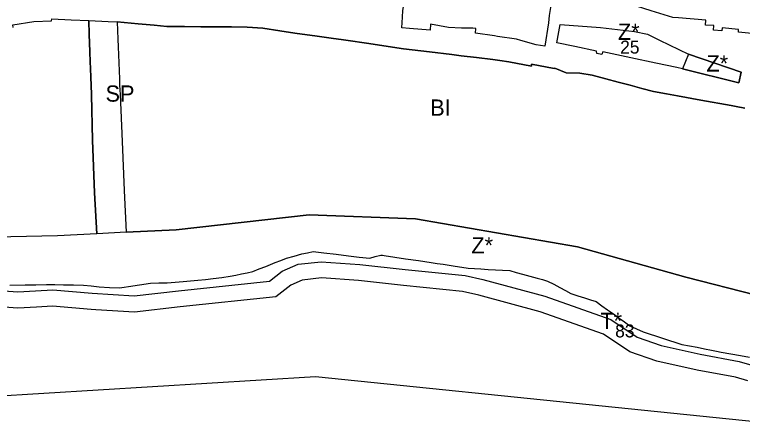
# Model space of a CAD drawing. Extents: x -521621 to -516769, y -1190068 to -1185078.
# Drawn here: x -519976.5 to -519527.8, y -1187499.7 to -1187252.5 of the extents above; entities that cross this region are included whole.
import ezdxf

# ---------------------------------------------------------------- set-up
doc = ezdxf.new("R2010")
doc.units = 0
for name, color, linetype in [('bydleni_s', 7, 'Continuous'), ('fpl_id', 7, 'Continuous'), ('s_zelen_n', 7, 'Continuous'), ('s_zelen_s', 7, 'Continuous'), ('sm_vyuziti_s', 7, 'Continuous'), ('v_infrastr_n', 7, 'Continuous'), ('v_infrastr_s', 7, 'Continuous')]:
    doc.layers.add(name, color=color, linetype=linetype)

msp = doc.modelspace()

# ---------------------------------------------------------------- linework, layer by layer
at = {"layer": 'bydleni_s'}
for p, q in [((-519953.48, -1187255.24), (-519941.71, -1187255.79)), ((-519890.55, -1187259.16), (-519900.38, -1187258.27)), ((-519876.99, -1187259.91), (-519881.28, -1187259.88)), ((-519871.68, -1187259.95), (-519876.99, -1187259.91)), ((-519861.65, -1187260.02), (-519871.68, -1187259.95)), ((-519851.16, -1187260.1), (-519861.65, -1187260.02)), ((-519842.67, -1187260.16), (-519851.16, -1187260.1)), ((-519833.02, -1187260.23), (-519842.67, -1187260.16)), ((-519823.53, -1187260.91), (-519833.02, -1187260.23)), ((-519732.96, -1187261.1), (-519737.73, -1187260.72)), ((-519720.15, -1187258.53), (-519720.29, -1187262.11)), ((-519708.93, -1187260.55), (-519720.15, -1187258.53)), ((-519720.29, -1187262.11), (-519732.96, -1187261.1)), ((-519781.28, -1187267.1), (-519791.4, -1187265.69)), ((-519773.71, -1187268.15), (-519781.28, -1187267.1)), ((-519746.21, -1187272.22), (-519758.17, -1187270.44)), ((-519736.81, -1187273.61), (-519746.21, -1187272.22)), ((-519720.78, -1187275.55), (-519736.81, -1187273.61)), ((-519691.74, -1187279.06), (-519701.12, -1187277.93)), ((-519681.7, -1187280.27), (-519691.74, -1187279.06)), ((-519657.79, -1187284.26), (-519671.74, -1187281.79)), ((-519628.05, -1187288.72), (-519636.38, -1187288.54)), ((-519620.33, -1187289.93), (-519628.05, -1187288.72)), ((-519612.06, -1187292.13), (-519620.33, -1187289.93)), ((-519604.31, -1187294.2), (-519612.06, -1187292.13)), ((-519596.95, -1187296.16), (-519604.31, -1187294.2)), ((-519589.7, -1187298.09), (-519596.95, -1187296.16)), ((-519582.68, -1187299.96), (-519589.7, -1187298.09)), ((-519574.6, -1187301.42), (-519582.68, -1187299.96)), ((-519567.81, -1187302.66), (-519574.6, -1187301.42)), ((-519553.37, -1187305.27), (-519567.81, -1187302.66))]:
    msp.add_line(p, q, dxfattribs=at)
for points in [[(-519737.73, -1187260.72), (-519737.35, -1187254.2), (-519737.12, -1187250.04), (-519735.38, -1187239.55), (-519734.51, -1187234.3), (-519732.25, -1187220.68), (-519722.78, -1187223.56), (-519717.7, -1187225.1)], [(-519674.48, -1187238.21), (-519667.79, -1187240.25), (-519663.98, -1187241.4), (-519648.55, -1187246.09), (-519645.83, -1187246.91), (-519646.91, -1187253.08), (-519647.41, -1187257.68), (-519649.63, -1187272.01), (-519654.84, -1187271.31), (-519664.38, -1187268.46), (-519667.11, -1187267.65), (-519678.78, -1187265.99), (-519680.67, -1187265.72), (-519692.44, -1187264.04), (-519692.17, -1187261.06), (-519693.98, -1187261.03), (-519700.87, -1187260.9), (-519708.93, -1187260.55)], [(-519567.27, -1187254.65), (-519570.68, -1187254.39), (-519584.02, -1187250.22)], [(-519964.67, -1187256.87), (-519953.79, -1187256.48), (-519953.48, -1187255.24)], [(-519941.71, -1187255.79), (-519930.82, -1187256.29), (-519930.51, -1187264.82), (-519930.13, -1187275.38), (-519929.9, -1187281.82), (-519929.76, -1187285.59)], [(-519550.28, -1187255.93), (-519567.27, -1187254.65)], [(-519540.33, -1187260.82), (-519540.49, -1187262.59), (-519545.51, -1187262.1), (-519545.47, -1187259.34), (-519550.52, -1187259.06), (-519550.28, -1187255.93)], [(-519977.48, -1187260.57), (-519977.63, -1187258.79), (-519964.67, -1187256.87)], [(-519900.38, -1187258.27), (-519913.35, -1187257.1), (-519912.91, -1187267.72), (-519912.71, -1187272.49)], [(-519881.28, -1187259.88), (-519882.64, -1187259.87), (-519890.55, -1187259.16)], [(-519813, -1187262.54), (-519823.53, -1187260.91)], [(-519802.25, -1187264.17), (-519803.78, -1187263.96), (-519813, -1187262.54)], [(-519791.4, -1187265.69), (-519802.25, -1187264.17)], [(-519530.1, -1187261.78), (-519540.33, -1187260.82)], [(-519519.83, -1187264.35), (-519530.22, -1187263.31), (-519530.1, -1187261.78)], [(-519758.17, -1187270.44), (-519772.22, -1187268.36), (-519773.71, -1187268.15)], [(-519912.71, -1187272.49), (-519912.31, -1187282.26), (-519911.9, -1187292.16), (-519911.84, -1187293.5)], [(-519701.12, -1187277.93), (-519706.87, -1187277.24), (-519720.78, -1187275.55)], [(-519671.74, -1187281.79), (-519677.39, -1187280.79), (-519681.7, -1187280.27)], [(-519643.9, -1187285.88), (-519657.87, -1187283.1), (-519657.79, -1187284.26)], [(-519929.76, -1187285.59), (-519929.56, -1187291.28), (-519929.38, -1187296.15)], [(-519636.38, -1187288.54), (-519643.36, -1187285.49), (-519643.9, -1187285.88)], [(-519929.38, -1187296.15), (-519929.17, -1187302.08), (-519928.48, -1187329.94)], [(-519911.84, -1187293.5), (-519911.74, -1187296.08), (-519911.5, -1187301.77)], [(-519911.5, -1187301.77), (-519910.14, -1187330.77)], [(-519534.65, -1187308.67), (-519553.37, -1187305.27)], [(-519526.24, -1187310.19), (-519531.59, -1187309.22), (-519534.65, -1187308.67)], [(-519928.48, -1187329.94), (-519927.32, -1187362.5), (-519925.74, -1187387.64), (-519950.01, -1187388.86), (-520026.94, -1187390.59)], [(-519910.14, -1187330.77), (-519908.88, -1187361.03), (-519907.62, -1187386.73), (-519876.89, -1187385.18), (-519794.89, -1187375.93), (-519729.3, -1187378.37), (-519629.4, -1187395.78), (-519562.67, -1187414.49), (-519519.39, -1187425.49)]]:
    msp.add_lwpolyline(points, dxfattribs=at)
at = {"layer": 's_zelen_n'}
msp.add_lwpolyline([(-519640.08, -1187258.64), (-519615.32, -1187260.57), (-519594.25, -1187262.96), (-519586.38, -1187264.66), (-519578.86, -1187268.28), (-519560.92, -1187276.93), (-519564.62, -1187286.03), (-519568.13, -1187285.28), (-519581.23, -1187282.49), (-519596.49, -1187279.24), (-519613.85, -1187275.54), (-519614.54, -1187277.08), (-519617.55, -1187276.62), (-519617.71, -1187275.08), (-519631.16, -1187272.32), (-519642.17, -1187270.06)], close=True, dxfattribs=at)
at = {"layer": 's_zelen_s'}
for points in [[(-519560.92, -1187276.93), (-519564.62, -1187286.03), (-519529.99, -1187294.55), (-519528.63, -1187288.11), (-519560.92, -1187276.93)], [(-519519.39, -1187425.49), (-519562.67, -1187414.49), (-519629.4, -1187395.78), (-519729.3, -1187378.37), (-519794.89, -1187375.93), (-519876.89, -1187385.18), (-519907.62, -1187386.73)], [(-519925.74, -1187387.64), (-519950.01, -1187388.86), (-520026.94, -1187390.59)], [(-519907.62, -1187386.73), (-519925.74, -1187387.64)], [(-519979.39, -1187419.45), (-519969.88, -1187419.22), (-519963.38, -1187419.06), (-519956.87, -1187418.91), (-519951.65, -1187419.02), (-519946.42, -1187419.12), (-519940.23, -1187419.25), (-519934.03, -1187419.37), (-519929.21, -1187419.87), (-519924.39, -1187420.37), (-519918.06, -1187420.72), (-519911.73, -1187421.07), (-519908.96, -1187420.63), (-519906.19, -1187420.19), (-519899.47, -1187419.12), (-519892.75, -1187418.06), (-519887.62, -1187417.98), (-519882.49, -1187417.9), (-519877.55, -1187417.5), (-519872.61, -1187417.09), (-519868.1, -1187416.73), (-519863.59, -1187416.36), (-519858.8, -1187415.78), (-519854.02, -1187415.2), (-519848.81, -1187414.54), (-519843.6, -1187413.89), (-519840.09, -1187413.16), (-519836.57, -1187412.42), (-519833.1, -1187411.69), (-519829.63, -1187410.96), (-519825.64, -1187409.39), (-519821.65, -1187407.81), (-519818.7, -1187406.65), (-519815.75, -1187405.49), (-519812.32, -1187404.14), (-519808.88, -1187402.78), (-519804.17, -1187401.39), (-519799.46, -1187400), (-519795.91, -1187399.34), (-519792.36, -1187398.69), (-519789.09, -1187399.07), (-519785.82, -1187399.46), (-519778.21, -1187400.35), (-519770.59, -1187401.25), (-519764.08, -1187402.02), (-519757.56, -1187402.78), (-519754.17, -1187401.78), (-519750.77, -1187400.77), (-519749.76, -1187400.92), (-519748.75, -1187401.07), (-519742.14, -1187402.05), (-519735.53, -1187403.03), (-519727.57, -1187404.22), (-519719.6, -1187405.4), (-519715.96, -1187405.96), (-519712.32, -1187406.51), (-519708.61, -1187407.07), (-519704.91, -1187407.64), (-519700.84, -1187408.26), (-519696.76, -1187408.88), (-519692.94, -1187409.12), (-519689.12, -1187409.37), (-519684.61, -1187409.67), (-519680.09, -1187409.96), (-519675.61, -1187410.15), (-519671.14, -1187410.34), (-519667.24, -1187411.5), (-519663.35, -1187412.66), (-519658.79, -1187413.89), (-519654.22, -1187415.12), (-519651.07, -1187415.97), (-519647.92, -1187416.82), (-519644.14, -1187418.84), (-519640.35, -1187420.87), (-519636.92, -1187422.71), (-519633.49, -1187424.54), (-519629.29, -1187425.87), (-519625.09, -1187427.2), (-519621.49, -1187428.34), (-519617.9, -1187429.48), (-519614.38, -1187432.01), (-519610.86, -1187434.53), (-519607.28, -1187437.09), (-519603.7, -1187439.66), (-519600.46, -1187442.02), (-519597.22, -1187444.37), (-519593.13, -1187446.22), (-519589.04, -1187448.07), (-519577.04, -1187451.97), (-519565.04, -1187455.87), (-519560.34, -1187456.72), (-519555.63, -1187457.56), (-519551.2, -1187458.53), (-519546.76, -1187459.49), (-519543.79, -1187460.11), (-519540.81, -1187460.73), (-519534.91, -1187461.73), (-519529.01, -1187462.73), (-519523.46, -1187463.74)]]:
    msp.add_lwpolyline(points, dxfattribs=at)
at = {"layer": 'sm_vyuziti_s'}
for points in [[(-519928.48, -1187329.94), (-519929.17, -1187302.08), (-519929.38, -1187296.15), (-519929.56, -1187291.28), (-519929.76, -1187285.59), (-519929.9, -1187281.82), (-519930.13, -1187275.38), (-519930.51, -1187264.82), (-519930.82, -1187256.29), (-519918.89, -1187256.84), (-519913.35, -1187257.1), (-519912.91, -1187267.72), (-519912.71, -1187272.49), (-519912.31, -1187282.26)], [(-519912.31, -1187282.26), (-519911.9, -1187292.16), (-519911.84, -1187293.5)], [(-519911.84, -1187293.5), (-519911.74, -1187296.08), (-519911.5, -1187301.77), (-519910.14, -1187330.77)], [(-519907.62, -1187386.73), (-519925.74, -1187387.64), (-519927.32, -1187362.5), (-519928.48, -1187329.94)], [(-519910.14, -1187330.77), (-519908.88, -1187361.03), (-519907.62, -1187386.73)]]:
    msp.add_lwpolyline(points, dxfattribs=at)
at = {"layer": 'v_infrastr_n'}
for points in [[(-519983.23, -1187422.8), (-519974.43, -1187423.57), (-519963.63, -1187422.96), (-519952.98, -1187422.19), (-519928.59, -1187424.35), (-519902.82, -1187426.04), (-519875.51, -1187422.8), (-519819.33, -1187416.94), (-519811.46, -1187410.77), (-519801.74, -1187406.44), (-519787.54, -1187404.9), (-519763.62, -1187406.6), (-519735.69, -1187409.69), (-519698.8, -1187413.39), (-519687.85, -1187415.86), (-519649.58, -1187426.2), (-519608.99, -1187440.55), (-519592.63, -1187451.35), (-519577.81, -1187456.6), (-519553.74, -1187462), (-519529.82, -1187466.32), (-519521.95, -1187468.64)], [(-519524.47, -1187478.32), (-519532.13, -1187476.06), (-519555.72, -1187471.8), (-519580.58, -1187466.23), (-519597.12, -1187460.37), (-519613.48, -1187449.57), (-519652.56, -1187435.75), (-519690.26, -1187425.57), (-519700.41, -1187423.28), (-519736.74, -1187419.63), (-519764.52, -1187416.56), (-519787.35, -1187414.94), (-519799.1, -1187416.21), (-519806.26, -1187419.4), (-519815.43, -1187426.59), (-519874.4, -1187432.74), (-519902.56, -1187436.08), (-519926.39, -1187434.52), (-519929.36, -1187434.32), (-519953.06, -1187432.22), (-519962.99, -1187432.94), (-519974.58, -1187433.59), (-519982.91, -1187432.87)], [(-519976.01, -1187540.05), (-519988.97, -1187497.77), (-519992.26, -1187488.06), (-519790.94, -1187475.66), (-519421.47, -1187513.5)]]:
    msp.add_lwpolyline(points, dxfattribs=at)
at = {"layer": 'v_infrastr_s'}
msp.add_line((-519833.02, -1187260.23), (-519823.53, -1187260.91), dxfattribs=at)
for points in [[(-519506.63, -1187270.05), (-519509.72, -1187269.62), (-519519.87, -1187268.2), (-519519.83, -1187264.35), (-519530.22, -1187263.31), (-519530.1, -1187261.78), (-519540.33, -1187260.82), (-519540.49, -1187262.59), (-519545.51, -1187262.1), (-519545.47, -1187259.34), (-519550.52, -1187259.06), (-519550.28, -1187255.93), (-519567.27, -1187254.65), (-519570.68, -1187254.39), (-519584.02, -1187250.22), (-519596.96, -1187246.17), (-519609.99, -1187242.09), (-519623.65, -1187237.81), (-519634.88, -1187234.3), (-519636.03, -1187233.94)], [(-519645.83, -1187246.91), (-519646.91, -1187253.08), (-519647.41, -1187257.68), (-519649.63, -1187272.01), (-519654.84, -1187271.31), (-519664.38, -1187268.46), (-519667.11, -1187267.65), (-519678.78, -1187265.99), (-519680.67, -1187265.72), (-519692.44, -1187264.04), (-519692.17, -1187261.06), (-519693.98, -1187261.03), (-519700.87, -1187260.9), (-519708.93, -1187260.55), (-519720.15, -1187258.53), (-519720.29, -1187262.11), (-519732.96, -1187261.1), (-519737.73, -1187260.72), (-519737.35, -1187254.2), (-519737.12, -1187250.04)], [(-519977.63, -1187258.79), (-519964.67, -1187256.87), (-519953.79, -1187256.48), (-519953.48, -1187255.24), (-519941.71, -1187255.79), (-519930.82, -1187256.29), (-519918.89, -1187256.84), (-519913.35, -1187257.1), (-519900.38, -1187258.27), (-519890.55, -1187259.16), (-519882.64, -1187259.87), (-519881.28, -1187259.88), (-519876.99, -1187259.91), (-519871.68, -1187259.95), (-519861.65, -1187260.02), (-519851.16, -1187260.1), (-519842.67, -1187260.16), (-519833.02, -1187260.23)], [(-519564.62, -1187286.03), (-519568.13, -1187285.28), (-519581.23, -1187282.49), (-519596.49, -1187279.24), (-519613.85, -1187275.54), (-519614.54, -1187277.08), (-519617.55, -1187276.62), (-519617.71, -1187275.08), (-519631.16, -1187272.32), (-519642.17, -1187270.06), (-519640.08, -1187258.64), (-519615.32, -1187260.57), (-519594.25, -1187262.96), (-519586.38, -1187264.66), (-519578.86, -1187268.28), (-519560.92, -1187276.93)], [(-519823.53, -1187260.91), (-519813, -1187262.54), (-519803.78, -1187263.96), (-519802.25, -1187264.17), (-519791.4, -1187265.69), (-519781.28, -1187267.1), (-519773.71, -1187268.15), (-519772.22, -1187268.36), (-519758.17, -1187270.44), (-519746.21, -1187272.22), (-519736.81, -1187273.61), (-519720.78, -1187275.55), (-519706.87, -1187277.24), (-519701.12, -1187277.93), (-519691.74, -1187279.06), (-519681.7, -1187280.27), (-519677.39, -1187280.79), (-519671.74, -1187281.79), (-519657.79, -1187284.26), (-519657.87, -1187283.1), (-519643.9, -1187285.88), (-519643.36, -1187285.49), (-519636.38, -1187288.54), (-519628.05, -1187288.72), (-519620.33, -1187289.93), (-519612.06, -1187292.13), (-519604.31, -1187294.2), (-519596.95, -1187296.16), (-519589.7, -1187298.09), (-519582.68, -1187299.96), (-519574.6, -1187301.42), (-519567.81, -1187302.66), (-519553.37, -1187305.27), (-519534.65, -1187308.67), (-519531.59, -1187309.22), (-519526.24, -1187310.19)], [(-519560.92, -1187276.93), (-519528.63, -1187288.11), (-519529.99, -1187294.55), (-519564.62, -1187286.03)]]:
    msp.add_lwpolyline(points, dxfattribs=at)

# ---------------------------------------------------------------- texts
at = {"layer": 'bydleni_s'}
msp.add_text('BI', height=10, dxfattribs=at).set_placement((-519720.24, -1187314.89))
at = {"layer": 'fpl_id'}
for s, p in [('25', (-519603.14, -1187276.61)), ('83', (-519606.23, -1187451.56))]:
    msp.add_text(s, height=8, dxfattribs=at).set_placement(p)
at = {"layer": 's_zelen_n'}
msp.add_text('Z*', height=10, dxfattribs=at).set_placement((-519604.55, -1187268.15))
at = {"layer": 's_zelen_s'}
for p in [(-519549.95, -1187287.66), (-519694.88, -1187399.79)]:
    msp.add_text('Z*', height=10, dxfattribs=at).set_placement(p)
at = {"layer": 'sm_vyuziti_s'}
msp.add_text('SP', height=10, dxfattribs=at).set_placement((-519920.43, -1187306.24))
at = {"layer": 'v_infrastr_n'}
msp.add_text('T*', height=10, dxfattribs=at).set_placement((-519615.36, -1187446.35))

doc.saveas('drawing.dxf')
